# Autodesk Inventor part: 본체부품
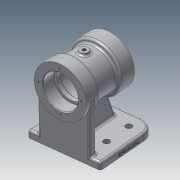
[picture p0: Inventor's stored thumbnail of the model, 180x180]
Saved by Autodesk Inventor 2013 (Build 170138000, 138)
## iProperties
Created: 2020-06
Part Number: 본체부품
Material: 알루미늄 6061
Document SubType Name: Modeling
Designer: CADCOM
Density: 2.71 g/cm^3
Mass: 727.643 g
Surface Area: 642.532 cm^2
Volume: 268.503 cm^3
Author: CADCOM
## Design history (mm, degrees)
sketch "스케치1"
  geometry: C1 r 35 at (0, 0); 1 further point
  constraints: 1 centre point, 1 coincident
  dimensions: "d0" = 70 diameter of C1
extrude "돌출1" new body sketch "스케치1" distance "d1" = 22; taper "d2" = 0 deg
sketch "스케치2"
  geometry: C1 r 35 at (0, 0) reference; C2 r 29 at (0, 0)
  constraints: 1 centre point, 1 coincident
  dimensions: "d3" = 58 diameter of C2
extrude "돌출2" join sketch "스케치2" distance "d4" = 34; taper "d5" = 0 deg
sketch "스케치3"
  geometry: C1 r 29 at (0, 0) reference; C2 r 35 at (0, 0)
  constraints: 1 centre point, 1 coincident
  dimensions: "d6" = 70 diameter of C2
extrude "돌출3" join sketch "스케치3" distance "d7" = 22; taper "d8" = 0 deg
node "작업 평면1"
sketch "스케치4"
  geometry: L1 (-35, 0)-(35, 0) reference; L2 (35, 0)-(35, -22) reference; L3 (-35, 0)-(-35, -22) reference; L4 (-35, -78)-(35, -78) reference; L5 (-35, -56)-(-35, -78) reference; L6 (35, -56)-(35, -78) reference; L7 (0, 0)-(0, -5); L8 (49, -5)-(-49, -5); L9 (-49, -5)-(-49, -95); L10 (-49, -95)-(49, -95); L11 (49, -95)-(49, -5)
  constraints: 10 end point, 3 parallel, 1 horizontal, 1 midpoint, 1 perpendicular
  dimensions: "d10" = 5 distance of L7.end L7.start; "d11" = 98 distance of L10.end L9.end; "d12" = 90 distance of L9.end L8.end
extrude "돌출4" join sketch "스케치4" distance "d13" = 10; taper "d14" = 0 deg
sketch "스케치5"
  geometry: L1 (-35, -22)-(-35, 0) reference; L2 (-35, 0)-(35, 0) reference; L3 (35, 0)-(35, -22) reference; L4 (35, -22)-(29, -22) reference; L5 (29, -22)-(29, -56) reference; L6 (29, -56)-(35, -56) reference; L7 (35, -56)-(35, -78) reference; L8 (35, -78)-(-35, -78) reference; L9 (-35, -78)-(-35, -56) reference; L10 (-35, -56)-(-29, -56) reference; L11 (-29, -56)-(-29, -22) reference; L12 (-29, -22)-(-35, -22) reference; L13 (-80, -5)-(-70, -5) reference; L14 (-70, -5)-(-70, -95) reference; L15 (-70, -95)-(-80, -95) reference; L16 (-80, -95)-(-80, -5) reference; L17 (-70, -95)-(-70, -83); L18 (-70, -83)-(-35, -70.261); L19 (-70, -83)-(-32.754, -83); 1 further point
  constraints: 6 end point, 2 point on line, 1 equal length, 1 horizontal
  dimensions: "d15" = 12 distance of L14.end L17.end; "d16" = 20 deg angle of L19 L18
  node "절단 모서리 투영1"
sketch "스케치6"
  geometry: L1 (-49, 5)-(49, 5) reference; L2 (-35, 5)-(35, 5); L3 (35, 5)-(35, 15); L4 (35, 15)-(-35, 15); L5 (-35, 15)-(-35, 5); 2 further points
  constraints: 8 end point, 2 midpoint, 2 parallel, 1 horizontal, 1 perpendicular
  dimensions: "d17" = 70 distance of L4.end L3.end; "d18" = 10 distance of L3.end L2.end
extrude "돌출5" join sketch "스케치6" stored distance "d19" = 0; taper "d20" = 0 deg
feature "리브1" dims "d21" = 1, "d22" = 10, "d23" = 0, "d24" = 0, "d25" = 1, "d26" = 1
sketch "스케치7"
  geometry: C1 r 35 at (0, 0) reference; C2 r 23.5 at (0, 0)
  constraints: 1 centre point, 1 coincident
  dimensions: "d27" = 47 diameter of C2
extrude "돌출6" cut sketch "스케치7" distance "d28" = 18; taper "d29" = 0 deg
sketch "스케치8"
  geometry: C1 r 23.5 at (0, 0) reference; C2 r 20 at (0, 0)
  constraints: 1 centre point, 1 coincident
  dimensions: "d30" = 40 diameter of C2
extrude "돌출7" cut sketch "스케치8" distance "d31" = 6; taper "d32" = 0 deg
sketch "스케치9"
  geometry: C1 r 20 at (0, 0) reference; C2 r 23 at (0, 0)
  constraints: 1 centre point, 1 coincident
  dimensions: "d33" = 46 diameter of C2
extrude "돌출8" cut sketch "스케치9" distance "d34" = 30; taper "d35" = 0 deg
sketch "스케치10"
  geometry: C1 r 35 at (0, 0) reference; C2 r 23.5 at (0, 0)
  constraints: 1 centre point, 1 coincident
  dimensions: "d36" = 47 diameter of C2
extrude "돌출9" cut sketch "스케치10" distance "d37" = 18; taper "d38" = 0 deg
sketch "스케치11"
  geometry: C1 r 23.5 at (0, 0) reference; C2 r 20 at (0, 0)
  constraints: 1 centre point, 1 coincident
  dimensions: "d39" = 40 diameter of C2
extrude "돌출10" cut sketch "스케치11" distance "d40" = 6; taper "d41" = 0 deg
sketch "스케치12"
  geometry: C1 r 35 at (0, 0) reference; A1 r 28.5 centre (0, 0) between (0, 28.5) and (0, -28.5); 2 further points
  constraints: 4 point on circle, 1 centre point, 1 coincident
  dimensions: "d42" = 57 diameter of A1
hole "구멍1" sketch "스케치12" at (0, 28.5), (0, -28.5), (28.5, 0), (-28.5, 0) diameter "d43" = 3.242; stored, may be unused: countersink angle "d47" = 90 deg, drill point angle "d49" = 118 deg; dims "d44" = 10, "d45" = 4, "d46" = 2, "d48" = 12
sketch "스케치13"
  geometry: C1 r 35 at (0, 0) reference; A1 r 28.5 centre (0, 0) between (0, 28.5) and (28.5, 0); 2 further points
  constraints: 4 point on circle, 1 centre point, 1 coincident
  dimensions: "d50" = 57 diameter of A1
hole "구멍2" sketch "스케치13" at (0, 28.5), (28.5, 0), (0, -28.5), (-28.5, 0) diameter "d51" = 3.242; stored, may be unused: countersink angle "d55" = 90 deg, drill point angle "d57" = 118 deg; dims "d52" = 10, "d53" = 4, "d54" = 2, "d56" = 12
node "작업 평면2"
sketch "스케치14"
  geometry: L1 (0, 0)-(0, -39); C1 r 6 at (0, -39)
  constraints: 2 end point, 1 centre point, 1 coincident, 1 vertical
  dimensions: "d59" = 39 distance of L1.start L1.end; "d60" = 12 diameter of C1
extrude "돌출11" join sketch "스케치14" stored distance "d61" = 6; taper "d62" = 0 deg
sketch "스케치15"
  geometry: C1 r 6 at (0, 0) reference; 2 further points
  constraints: 1 coincident
hole "구멍3" sketch "스케치15" at (0, 0) diameter "d63" = 5.188; stored, may be unused: countersink angle "d67" = 90 deg, drill point angle "d69" = 0 deg; dims "d64" = 10, "d65" = 4, "d66" = 2, "d68" = 12
fillet "모깎기1" dims "d70" = 20
sketch "스케치16"
  geometry: L1 (29, 95)-(-29, 95) reference; L2 (-29, 75)-(-29, 39); L3 (29, 75)-(29, 39); A1 r 20 centre (-29, 75) between (-29, 95) and (-49, 75) reference; A2 r 20 centre (29, 75) between (49, 75) and (29, 95) reference; 5 further points
  constraints: 4 coincident, 4 end point, 1 parallel, 1 perpendicular
  dimensions: "d71" = 36 distance of L2.start L2.end; "d72" = 36 distance of L3.start L3.end
hole "구멍4" sketch "스케치16" at (-29, 75), (-29, 39), (29, 39), (29, 75) diameter "d73" = 9; stored, may be unused: countersink angle "d77" = 90 deg, drill point angle "d79" = 0 deg; dims "d74" = 10, "d75" = 4, "d76" = 2, "d78" = 12
chamfer "모따기1" distance "d80" = 1; stored, may be unused: second distance "d81" = 2, angle "d82" = 45 deg
fillet "모깎기2" dims "d83" = 0.3
fillet "모깎기4" dims "d85" = 3
fillet "모깎기5" dims "d86" = 3
fillet "모깎기6" dims "d87" = 3
fillet "모깎기7" dims "d88" = 3
fillet "모깎기9" dims "d90" = 3
fillet "모깎기10" dims "d91" = 3
fillet "모깎기11" dims "d92" = 3
sketch "스케치17"
  geometry: L1 (0, 0)-(67, 0) reference; L2 (-3, 7)-(-3, 0) reference; 2 further points
  constraints: 1 other
  dimensions: "d93" = 45 distance from line of L2 point (42, 4); "d94" = 4 distance from line of L1 point (42, 4)
feature "엠보싱1" sketch "스케치17" dims "d0" = 70, "d95" = 0.5, "d96" = 0
fillet "모깎기12" dims "d97" = 3
fillet "모깎기13" dims "d98" = 3
node "솔리드1"
other parameters: "d58" = 32
